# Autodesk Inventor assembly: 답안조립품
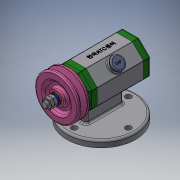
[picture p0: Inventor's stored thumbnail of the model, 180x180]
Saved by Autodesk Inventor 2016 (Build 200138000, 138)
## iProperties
Created: 2021-02
Part Number: 답안조립품
Material: 일반
Document SubType Name: Weldment
Designer: WIN7
Weld Material: Welded Aluminum-6061
Author: WIN7
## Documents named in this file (14)
- C:\Users\WIN7\Desktop\710204V1001\답안조립품.iam
- C:\Users\WIN7\Desktop\710204V1001\본체.ipt
- C:\Users\WIN7\Desktop\710204V1001\축.ipt
- C:\Users\WIN7\Desktop\710204V1001\베어링 15 x 32 x 9.ipt
- C:\Users\WIN7\Desktop\710204V1001\뒤커버.ipt
- C:\Users\WIN7\Desktop\710204V1001\앞커버.ipt
- C:\Users\WIN7\Desktop\710204V1001\오일 실 15 25 7.ipt
- C:\Users\WIN7\Desktop\710204V1001\볼트 M4 x 12.ipt
- C:\Users\WIN7\Desktop\710204V1001\V벨트풀리.ipt
- C:\Users\WIN7\Desktop\710204V1001\키 3 x 3 x 12.ipt
- C:\Users\WIN7\Desktop\710204V1001\와셔 8x17.ipt
- C:\Users\WIN7\Desktop\710204V1001\스프링와셔 8.ipt
- C:\Users\WIN7\Desktop\710204V1001\너트 M8.ipt
- C:\Users\WIN7\Desktop\710204V1001\고무캡.ipt
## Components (2 placed, 2 different names)
1. V벨트풀리:1
2. 고무캡:1
